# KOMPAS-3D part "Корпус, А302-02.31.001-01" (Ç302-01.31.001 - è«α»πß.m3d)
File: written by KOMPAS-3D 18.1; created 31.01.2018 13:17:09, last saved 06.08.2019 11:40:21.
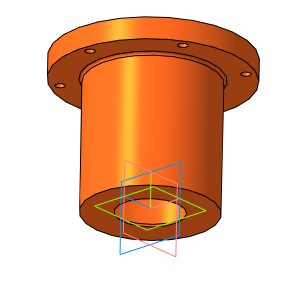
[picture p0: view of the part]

Document properties: Автор: Милов; Полное имя файла: D:\Мембранные насосы\Мембранный электропривод\А302-00.00.000 - ASTRA-302 (МЭ200)\3Д ПВХ\А302-01.31.001 - Корпус.m3d

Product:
- Part/product: Корпус  | designation А302-02.31.001-01
    Масса: 0.260351
    Раздел спецификации: Детали
    Форматы листов документа: A4
- Part/product: Корпус  | designation А302-02.31.001
    Масса: 0.300009
    Раздел спецификации: Детали
    Форматы листов документа: A4
    Комментарий: С интегрированными стаканами.
- Part/product: Корпус  | designation А302-01.31.001
    Масса: 0.575768
    Раздел спецификации: Детали
    Форматы листов документа: A4
    source file: А302-01.31.001 - Корпус.cdw

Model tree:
1. Эскиз:1
2. Операция вращения:1
     Угол 1 = 360
3. Фаска:5  (with: Операция вращения:1)
     Угол = 45; Длина 1 = 3; Длина 2 = 3
4. Эскиз:6  (with: Операция вращения:1)
5. Вырезать элемент выдавливания:2
6. Массив по концентрической сетке:2  (with: Вырезать элемент выдавливания:2, Эскиз:6)  (6 pattern instances)
     Шаг 2 = 360
7. Фаска:6  (with: Операция вращения:1)
     Угол = 45; Длина 1 = 1; Длина 2 = 1
8. Скругление:1  (with: Операция вращения:1)
     Радиус = 2
9. Сечение поверхностью:2
10. Эскиз:2
11. Вырезать элемент выдавливания:1
     Расстояние 1 = 9
12. Фаска:1
     Угол = 45; Длина 1 = 1; Длина 2 = 1
13. Эскиз:3
14. Операция выдавливания:1
     Расстояние 2 = 14
15. Эскиз:5
16. Отверстие:1
     Глубина выреза = 20; Диаметр отверстия = 6; Угол конуса торца = 118; Координата Y = 47
17. Массив по концентрической сетке:1  (with: Отверстие:1, Эскиз:5)  (6 pattern instances)
     Шаг 2 = 360
18. Фаска:3
     Угол = 45; Длина 1 = 1; Длина 2 = 1
19. Фаска:4
     Угол = 45; Длина 1 = 1; Длина 2 = 1
20. Элемент выдавливания:1
     Расстояние 1 = 25

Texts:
  Линейный размер с обрывом

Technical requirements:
  Gost Type A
